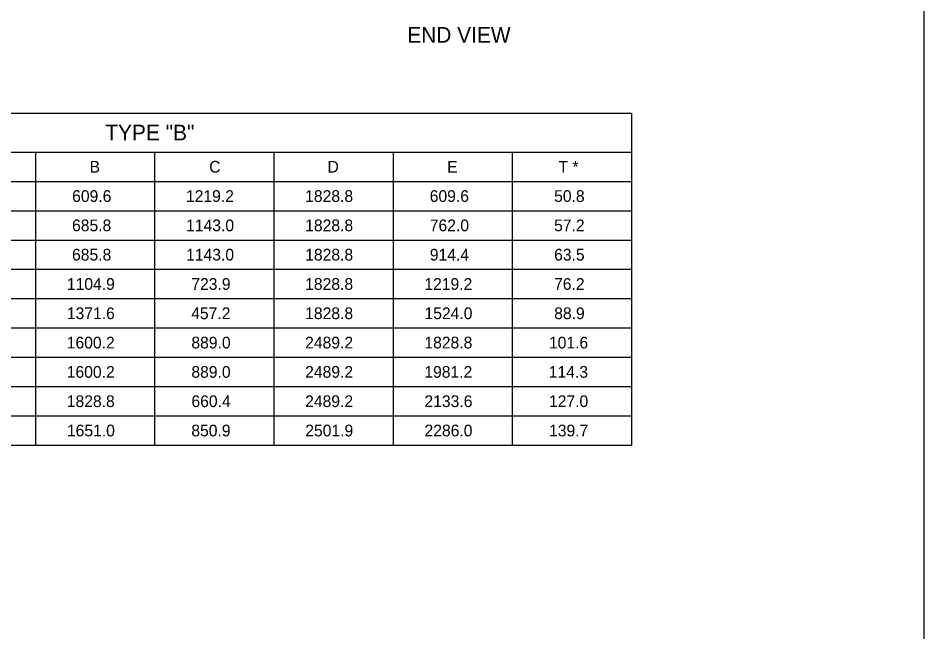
# Model space of a CAD drawing. Extents: x 49991.4 to 50022.1, y 49985 to 50011.4.
# Drawn here: x 50012.115 to 50016.75, y 49992.021 to 49995.163 of the extents above; entities that cross this region are included whole.
import ezdxf

# ---------------------------------------------------------------- set-up
doc = ezdxf.new("R2010")
doc.units = 0
doc.layers.add('Level 1', color=7, linetype='Continuous')
doc.layers.add('Level 2', color=7, linetype='Continuous')

msp = doc.modelspace()

# ---------------------------------------------------------------- linework, layer by layer
at = {"layer": 'Level 1'}
msp.add_lwpolyline([(49999.3835, 49998.9992), (50016.7501, 49998.9992), (50016.7501, 49987.7988), (49999.3835, 49987.7988)], close=True, dxfattribs=at)
at = {"layer": 'Level 2'}
for p, q in [((50010.3734, 49994.677), (50015.2534, 49994.677)), ((50015.2534, 49994.677), (50015.2534, 49992.977)), ((50015.2534, 49994.677), (50015.2534, 49992.977)), ((50010.3734, 49994.477), (50015.2534, 49994.477)), ((50012.2034, 49994.477), (50012.2034, 49992.977)), ((50012.8134, 49994.477), (50012.8134, 49992.977)), ((50013.4234, 49994.477), (50013.4234, 49992.977)), ((50014.0334, 49994.477), (50014.0334, 49992.977)), ((50014.6434, 49994.477), (50014.6434, 49992.977)), ((50010.3734, 49994.327), (50015.2534, 49994.327)), ((50010.3734, 49994.177), (50015.2534, 49994.177)), ((50010.3734, 49994.027), (50015.2534, 49994.027)), ((50010.3734, 49993.877), (50015.2534, 49993.877)), ((50010.3734, 49993.727), (50015.2534, 49993.727)), ((50010.3734, 49993.577), (50015.2534, 49993.577)), ((50010.3734, 49993.427), (50015.2534, 49993.427)), ((50010.3734, 49993.277), (50015.2534, 49993.277)), ((50010.3734, 49993.127), (50015.2534, 49993.127)), ((50010.3734, 49992.977), (50015.2534, 49992.977))]:
    msp.add_line(p, q, dxfattribs=at)

# ---------------------------------------------------------------- texts
for s, height, p in [('END VIEW', 0.08, (50014.1061, 49995.037)), ('TYPE "B"', 0.08, (50012.5608, 49994.537)), ('B', 0.06, (50012.4807, 49994.372)), ('C', 0.06, (50013.0929, 49994.372)), ('D', 0.06, (50013.6981, 49994.372)), ('E', 0.06, (50014.3104, 49994.372)), ('T *', 0.06, (50014.8802, 49994.372)), ('609.6', 0.06, (50012.3913, 49994.222)), ('1219.2', 0.06, (50012.9737, 49994.222)), ('1828.8', 0.06, (50013.5838, 49994.222)), ('609.6', 0.06, (50014.2213, 49994.222)), ('50.8', 0.06, (50014.8578, 49994.222)), ('685.8', 0.06, (50012.3908, 49994.072)), ('1143.0', 0.06, (50012.9746, 49994.072)), ('1828.8', 0.06, (50013.5839, 49994.072)), ('762.0', 0.06, (50014.2215, 49994.072)), ('57.2', 0.06, (50014.8576, 49994.072)), ('685.8', 0.06, (50012.3908, 49993.922)), ('1143.0', 0.06, (50012.9746, 49993.922)), ('1828.8', 0.06, (50013.5839, 49993.922)), ('914.4', 0.06, (50014.2218, 49993.922)), ('63.5', 0.06, (50014.8578, 49993.922)), ('1104.9', 0.06, (50012.3643, 49993.772)), ('723.9', 0.06, (50013.0013, 49993.772)), ('1828.8', 0.06, (50013.5838, 49993.772)), ('1219.2', 0.06, (50014.1937, 49993.772)), ('76.2', 0.06, (50014.8576, 49993.772)), ('1371.6', 0.06, (50012.3643, 49993.622)), ('457.2', 0.06, (50013.0006, 49993.622)), ('1828.8', 0.06, (50013.5838, 49993.622)), ('1524.0', 0.06, (50014.1946, 49993.622)), ('88.9', 0.06, (50014.8582, 49993.622)), ('1600.2', 0.06, (50012.3637, 49993.472)), ('889.0', 0.06, (50013.0015, 49993.472)), ('2489.2', 0.06, (50013.5837, 49993.472)), ('1828.8', 0.06, (50014.1939, 49993.472)), ('101.6', 0.06, (50014.8313, 49993.472)), ('1600.2', 0.06, (50012.3637, 49993.322)), ('889.0', 0.06, (50013.0015, 49993.322)), ('2489.2', 0.06, (50013.5837, 49993.322)), ('1981.2', 0.06, (50014.1937, 49993.322)), ('114.3', 0.06, (50014.8306, 49993.322)), ('1828.8', 0.06, (50012.3639, 49993.172)), ('660.4', 0.06, (50013.0018, 49993.172)), ('2489.2', 0.06, (50013.5837, 49993.172)), ('2133.6', 0.06, (50014.1943, 49993.172)), ('127.0', 0.06, (50014.8315, 49993.172)), ('1651.0', 0.06, (50012.3646, 49993.022)), ('850.9', 0.06, (50013.0013, 49993.022)), ('2501.9', 0.06, (50013.5843, 49993.022)), ('2286.0', 0.06, (50014.1946, 49993.022)), ('139.7', 0.06, (50014.832, 49993.022))]:
    msp.add_text(s, height=height, dxfattribs=at).set_placement(p)

doc.saveas('drawing.dxf')
